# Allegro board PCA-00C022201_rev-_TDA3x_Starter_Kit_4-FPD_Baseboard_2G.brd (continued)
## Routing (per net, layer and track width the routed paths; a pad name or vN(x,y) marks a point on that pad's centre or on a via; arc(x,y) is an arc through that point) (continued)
VOUT1_D23: length 98.7
  TOP w0.127: v1(40.01,8.47) J14.25 ; U16.36 v1(99.75,59.18)
  INNER1 w0.127: v1(40.01,8.47) 40.01,10.87 40.26,11.11 40.26,13.98 48.07,21.79 v1(51.64,21.79) 51.64,22.15 51.05,22.73 51.05,31.5 55.37,35.81 59.94,35.81 86.49,62.36 97.79,62.36 99.75,60.4 v1(99.75,59.18)
  BOTTOM w0.127: J13.53 51.39,22.04 v1(51.64,21.79)
VOUT1_DE: length 93.2
  TOP w0.127: v1(92.84,42.86) 93.54,43.56 93.79,43.56 94.25,44.02 U16.2 ; v1(51.94,11.24) 51.94,12.51 51.31,13.14 46.8,13.14 45.01,11.36 J14.45
  INNER1 w0.127: v1(51.94,11.24) 51.94,10.44 51.82,10.31 51.69,10.31 51.56,10.19 51.56,9.93 51.69,9.81 51.82,9.81 51.94,9.68 51.94,9.53 52.7,8.76 52.96,8.76 53.09,8.89 53.09,9.27 53.21,9.4 53.47,9.4 53.59,9.27 53.59,8.89 53.72,8.76 53.98,8.76 54.1,8.89 54.1,9.27 54.23,9.4 54.48,9.4 54.61,9.27 54.61,8.89 54.74,8.76 54.99,8.76 55.12,8.89 55.12,9.27 55.24,9.4 55.5,9.4 55.63,9.27 55.63,8.89 55.75,8.76 56.01,8.76 62.48,15.24 66.67,15.24 74.42,22.99 74.42,23.62 75.06,24.26 75.06,30.48 75.18,30.61 75.69,30.61 75.82,30.73 75.82,30.99 75.69,31.11 75.18,31.11 75.06,31.24 75.06,31.5 86.42,42.86 87.57,42.86 87.7,42.99 87.7,44.07 87.83,44.2 88.08,44.2 88.21,44.07 88.21,42.99 88.34,42.86 88.59,42.86 88.72,42.99 88.72,44.32 88.84,44.45 89.1,44.45 89.23,44.32 89.23,42.99 89.35,42.86 89.61,42.86 89.73,42.99 89.73,44.32 89.86,44.45 90.11,44.45 90.24,44.32 90.24,42.99 90.37,42.86 90.62,42.86 90.75,42.99 90.75,44.32 90.88,44.45 91.13,44.45 91.26,44.32 91.26,42.99 91.38,42.86 91.64,42.86 91.77,42.99 91.77,43.69 91.89,43.81 92.15,43.81 92.27,43.69 92.27,42.99 92.4,42.86 v1(92.84,42.86)
VOUT1_FLD: length 45.5
  TOP w0.127: U48.19 80.04,20.61 79.82,20.83 R237.2 79.82,22.03 78.49,23.37 v1(75.06,23.37) ; J14.53 47.01,10.95 47.88,11.81 49.97,11.81 v1(50.55,11.24)
  INNER1 w0.127: v1(75.06,23.37) 75.06,22.99 66.87,14.8 62.67,14.8 56.13,8.26 52.58,8.26 50.55,10.29 v1(50.55,11.24)
VOUT1_HSYNC: length 92.5
  TOP w0.127: v1(94.74,43.56) 95.25,44.07 U16.4 ; v1(51.24,10.79) 51.24,11.3 50.29,12.26 47.18,12.26 46.01,11.09 J14.49
  INNER1 w0.127: v1(51.24,10.79) 51.24,11.3 51.75,11.81 52.32,11.81 52.58,11.56 52.58,10.13 52.43,9.98 52.43,9.8 52.61,9.62 52.79,9.62 53.08,9.91 53.08,11.56 53.2,11.68 53.46,11.68 53.58,11.56 53.58,10.03 53.71,9.91 53.96,9.91 54.09,10.03 54.09,11.56 54.22,11.68 54.47,11.68 54.6,11.56 54.6,10.03 54.73,9.91 54.98,9.91 55.11,10.03 55.11,11.56 55.23,11.68 55.49,11.68 55.62,11.56 55.62,10.03 55.74,9.91 56.52,9.91 56.72,10.11 56.72,10.29 56.14,10.87 56.14,11.05 56.32,11.23 56.5,11.23 56.93,10.79 57.4,10.79 62.29,15.68 66.48,15.68 73.91,23.11 73.91,23.75 74.61,24.45 74.61,31.69 86.3,43.37 87.95,45.02 94.61,45.02 94.81,45.21 94.81,46.41 94.93,46.54 95.19,46.54 95.31,46.41 95.31,44.13 v1(94.74,43.56)
VOUT1_VSYNC: length 93.7
  TOP w0.127: U16.5 v1(95.75,43.69) ; J14.47 45.51,11.22 46.99,12.7 50.55,12.7 v1(51.24,12)
  INNER1 w0.127: v1(95.75,43.69) 95.76,43.7 95.76,46.74 95.19,47.31 95.19,54.99 95.06,55.12 94.81,55.12 94.68,54.99 94.68,47.31 94.11,46.74 94.11,45.85 93.73,45.47 87.76,45.47 86.11,43.81 86.11,43.81 74.17,31.88 74.17,24.64 73.41,23.88 73.41,23.24 66.29,16.13 62.1,16.13 57.4,11.43 57.02,11.43 56.26,12.19 51.44,12.19 v1(51.24,12)
WARM_RESETN: length 1.6
  TOP w0.152: TP76.1 86.02,11.43 J14.169
XREF_CLK/TIMER3: length 43.4
  TOP w0.127: J14.124 v1(74.52,4.78) ; U9.44 91.56,28.18 91,27.62 90.3,27.62 TP14.1 89.28,27.43 R121.2
  BOTTOM w0.127: TP14.1 89.53,27.43 86.66,24.56 86.66,8.24 85.98,7.56 85.98,4.19 85.47,3.68 75.61,3.68 v1(74.52,4.78)
N16778655: length 1.3
  TOP w0.305: C1.1 110.93,15.37 110.79,15.51 U1.1
N16778658: length 7.3
  TOP w0.305: C1.2 v1(111.7,13.78)
  BOTTOM w0.305: v1(111.7,13.78) 107,13.78 v1(105.66,15.11)
N16779093: length 2.6
  TOP w0.305: R12.1 105.49,19.74 105.49,18.77 C6.1 105.59,18.67 106.11,18.67 106.39,18.39 U1.7
N16779143: length 1.2
  TOP w0.305: R13.1 U1.5
N16779358: length 1.3
  TOP w0.305: C5.1 111.5,18.39 U1.4
N16784059: length 3
  BOTTOM w0.381: U3.14 16.75,59.65 17.41,58.98 R28.1 R26.2
N16784098: length 1.6
  BOTTOM w0.254: U3.3 8.67,60.95 R24.2
N16784610: length 5.5
  BOTTOM w0.381: U3.13 17.24,60.3 17.78,59.75 R30.1
N16784791: length 11
  INNER2 w0.381: v2(14.22,58.42) 14.8,58.99 v1(23.18,58.99)
  BOTTOM w0.381: R30.2 R31.1 v1(23.18,58.99)
  vias: v1(12.06,63.5) v1(12.06,62.55) v1(12.06,61.59) v1(12.06,60.64) v1(12.06,59.69) v1(12.95,63.5) v1(12.95,62.55) v1(12.95,61.59) v1(12.95,60.64) v1(12.95,59.69) v1(13.84,63.5) v1(13.84,62.55) v1(13.84,61.59) v1(13.84,60.64) v1(13.84,59.69) v2(7.11,58.93) v2(7.56,68.33) v2(7.56,67.31) v2(7.56,66.29) v2(7.56,65.28) v2(8.57,68.33) v2(8.57,67.31) v2(8.57,66.29) v2(8.57,65.28) v2(8.64,58.93) v2(9.59,68.33) v2(9.59,67.31) v2(9.59,66.29) v2(9.59,65.28) v2(10.6,68.33) v2(10.6,67.31) v2(10.6,66.29) v2(10.6,65.28) v2(10.79,58.67) v2(11.62,68.33) v2(11.62,67.31) v2(11.62,66.29) v2(11.62,65.28) v2(11.94,58.67) v2(12.64,68.33) v2(12.64,67.31) v2(12.64,66.29) v2(12.64,65.28) v2(13.08,58.42) v2(13.08,57.15) v2(13.65,68.33) v2(13.65,67.31) v2(13.65,66.29) v2(13.65,65.28) v2(14.22,57.15) v2(14.67,68.33) v2(14.67,67.31) v2(14.67,66.29) v2(14.67,65.28) v2(15.37,57.15) v2(15.68,68.33) v2(15.68,67.31) v2(15.68,66.29) v2(15.68,65.28)
N16788418: length 1.8
  TOP w0.203: U5.9 98.4,4.09 98.99,3.49 C25.2
N16788506: length 1.3
  TOP w0.292: C22.2 97.15,3.18 U5.7
N16788509: length 1.6
  TOP w0.292: C22.1 98.32,2.9 97.65,3.49 U5.8
N16799359: length 1.1
  BOTTOM w0.127: R69.2 6.67,17.85 C77.1
N16799508: length 5.4
  BOTTOM w0.305: R63.2 7.82,13.46 7.82,9.25 L13.2
N16800770: length 1.1
  BOTTOM w0.127: C78.1 6.67,30.55 R70.2
N16800854: length 5.5
  BOTTOM w0.305: R65.2 7.82,26.16 7.82,21.93 L15.2
N16801557: length 1.1
  BOTTOM w0.127: R77.2 6.67,43.25 C91.1
N16801641: length 5.2
  BOTTOM w0.305: L23.2 7.82,34.63 7.82,38.84 R71.2
N16802378: length 1.1
  BOTTOM w0.127: R78.2 6.67,55.95 C92.1
N16802462: length 5.5
  BOTTOM w0.305: R73.2 7.82,51.51 7.82,47.3 L25.2
N16805253: length 1.3
  BOTTOM w0.152: R59.2 33.65,38.82 U7.1
N16808896: length 5.6
  BOTTOM w0.127: U6.5 31.9,29.8 31.9,30.99 30.82,32.07 R45.2
N16808937: length 4.8
  BOTTOM w0.152: R42.2 32.96,33.34 32.18,32.56 TP4.1 32.41,31.53 U6.6
N16828608: length 2.1
  TOP w0.152: U10.1 v1(98.3,67.5)
  BOTTOM w0.152: v1(98.3,67.5) 97.41,67.5 R90.2
N16828611: length 1.9
  TOP w0.152: U10.4 v1(98.3,63.69)
  BOTTOM w0.152: v1(98.3,63.69) 99.06,63.69 R91.2
N16829078: length 4.2
  TOP w0.381: R93.2 107.51,64.83 108.01,65.34 v1(108.01,65.6) 108.01,65.91 107.57,66.36 R92.2
  BOTTOM w0.381: C111.1 v1(108.01,65.6)
N16848362: length 2.4
  BOTTOM w0.152: J13.15 60.89,20.96 R112.2
N16871816: length 2.3
  TOP w0.254: U9.12 94.67,36.13 95.25,36.7 v1(95.25,37.01)
  BOTTOM w0.508: v1(95.25,37.01) R117.1
N16872796: length 2.6
  TOP w0.203: U13.8 v1(93.32,21.7)
  BOTTOM w0.254: R118.1 93.32,23.87 v1(93.32,21.7)
N16872856: length 4.7
  TOP w0.203: U13.5 93.46,19.82 94.44,18.85 95.15,18.85 95.63,18.36 R119.1 96.01,18.54 R120.2
N16877045: length 1.2
  TOP w0.127: U14.3 94.55,39.98 R233.1
N16921638: length 2.7
  BOTTOM w0.254: R25.2 17.97,60.64 17.67,60.95 U3.12
N16945191: length 1.5
  BOTTOM w0.305: C150.1 J24.12
N16950158: length 2.5
  BOTTOM w0.305: C151.1 J24.6
N16950163: length 2.5
  BOTTOM w0.305: J24.1 C152.1
N16950168: length 1.5
  BOTTOM w0.305: J24.7 C153.1
N16959967: length 3
  TOP w0.152: U16.3 v1(94.75,44.45)
  BOTTOM w0.152: v1(94.75,44.45) 95.5,44.45 95.89,44.83 R131.1
N16959972: length 3.4
  TOP w0.152: U16.10 v1(98.25,44.45)
  BOTTOM w0.152: R130.1 98.25,45.26 v1(98.25,44.45) 98.25,43.26 R134.1
N16959998: length 2
  TOP w0.127: U16.15 v1(100.75,44.58)
  BOTTOM w0.127: v1(100.75,44.58) 101.13,44.2 R132.2
N16960003: length 4
  TOP w0.127: U16.14 100.25,44.34 100.52,44.07 101.98,44.07 102.23,43.82 R133.2
N16960049: length 2.3
  TOP w0.152: R135.1 99.75,43.38 U16.13
N16962010: length 1.1
  TOP w0.279: 103.25,48.18 v1(104.39,48.18)
N16974466: length 2.1
  TOP w0.152: J21.9 87.3,56.83 v1(88.01,56.83)
  BOTTOM w0.152: v1(88.01,56.83) R151.1
N16989017: length 2.8
  TOP w0.152: U10.8 v1(101.35,67.5)
  BOTTOM w0.152: R166.1 100.52,67.5 v1(101.35,67.5) 102.17,67.5 R89.2
N17023402: length 8.5
  TOP w0.305: R10.2 R14.1 102.21,20.22 102.63,20.64 106.17,20.64 106.89,19.92 U1.6
N17041661: length 5.8
  TOP w0.152: R180.2 87.76,27.56 88.33,28.13 90.87,28.13 91.19,28.45 91.19,29.08 91.05,29.21 U9.43
N17043205: length 1.7
  TOP w0.305: D12.C v1(90.68,26.86)
  BOTTOM w0.305: v1(90.68,26.86) 90.68,26.16 R181.1
N17043208: length 1.5
  BOTTOM w0.305: J24.13 R182.1
N17043211: length 1.5
  BOTTOM w0.305: R183.1 J24.16
N17061008: length 2.4
  TOP w0.292: 34.98,14.1 34.98,14.1 U21.3
  TOP w0.381: TP44.1 34.98,13.54 R184.2
N17061570: length 1.2
  TOP w0.292: C179.1 39.39,14.1 U21.6
N17062531: length 2.7
  TOP w0.152: U22.2 v1(26.92,3.42)
  BOTTOM w0.152: R194.2 27.68,3.42 v1(26.92,3.42) 26.17,3.42 R193.1
N17062635: length 7.5
  TOP w0.152: U22.21 23.9,4.72 v1(26.16,6.99)
  BOTTOM w0.152: v1(26.16,6.99) R195.1 R196.2
N17083264: length 2
  TOP w0.152: R222.1 v1(42.99,42.55)
  BOTTOM w0.152: v1(42.99,42.55) 42.99,42.05 42.84,41.9 U28.4
N17084179: length 3.3
  TOP w0.152: J14.11 36.51,11.24 36.83,11.56 TP50.1
N17084298: length 1.8
  TOP w0.152: TP51.1 39.62,10.92 39.51,10.81 J14.23
N17084336: length 1.8
  TOP w0.152: J14.12 36.51,1.84 TP52.1
N17084566: length 2
  TOP w0.152: TP53.1 39.01,2.31 J14.22
N17086992: length 2.1
  TOP w0.152: J14.126 75.02,2.63 TP54.1
N17087001: length 1.8
  TOP w0.152: TP55.1 75.52,1.86 J14.128
N17088234: length 4.2
  BOTTOM w0.61: R223.1 123.19,3.81 MH1.1
N17088237: length 4.2
  BOTTOM w0.61: MH2.1 4.57,3.05 R224.1
N17088240: length 4.1
  TOP w0.61: R225.1 123.19,66.04 MH3.1
N17088243: length 4.3
  BOTTOM w0.61: MH4.1 3.81,64.14 R226.1
N17088661: length 4.1
  BOTTOM w0.61: R227.1 92.38,14.61 MH5.1
N17088663: length 4.1
  BOTTOM w0.61: R228.1 MH6.1
N17088675: length 4.6
  BOTTOM w0.61: MH7.1 92.38,63.62 R229.1
N17088677: length 4.1
  BOTTOM w0.61: MH8.1 R230.1
N17350751: length 13.7
  TOP w0.406: J23.7 19.74,65.73 J23.5
  BOTTOM w0.254: J23.9 19.42,68.4 ; J23.9 16.97,68.4 ; J23.9 18.19,67.27 ; J23.6 24.97,65.4 ; J23.6 23.57,65.4 ; J23.6 24.27,66.2 ; J23.8 26.72,68.4 ; J23.8 25.49,67.27 ; J23.8 24.27,68.4 ; 18.72,65.4 J23.7 ; J23.7 19.42,64.6 ; J23.7 19.42,66.2 ; J23.7 20.12,65.4
N17371221: length 2.3
  BOTTOM w0.152: U38.6 33.79,45.67 33.46,45.34 R102.1
N17371356: length 2.8
  BOTTOM w0.152: R105.1 35.75,45.28 35.5,45.53 35.12,45.53 34.79,45.85 U38.4
N17389734: length 2.2
  TOP w0.508: R249.2 26.34,61.54 R251.1 26.35,60.49 R247.1
N17389895: length 2.4
  TOP w0.508: R250.2 8.45,61.34 R248.1 R252.1
N17515572: length 1.9
  TOP w0.305: D18.C v1(101.41,2.03)
  BOTTOM w0.305: v1(101.41,2.03) 101.16,2.28 Q7.3
N17515594: length 1.8
  TOP w0.305: D18.A v1(103.53,2.92)
  BOTTOM w0.305: v1(103.53,2.92) 103.53,2.06 R259.2
N17515834: length 6.8
  TOP w0.305: D17.C v1(104.52,2.03)
  BOTTOM w0.305: v1(104.52,2.03) 104.52,2.86 101.16,6.22 Q8.3
N17515881: length 1.8
  TOP w0.305: D17.A v1(106.64,2.92)
  BOTTOM w0.305: v1(106.64,2.92) 106.64,2.06 R260.2
N17688900: length 1.7
  TOP w0.152: SW2.7 v1(9.65,3.17)
  BOTTOM w0.152: R204.2 v1(9.65,3.17)
N17688914: length 1.7
  TOP w0.152: 8.64,1.91 v1(9.65,1.91)
  BOTTOM w0.152: R203.1 v1(9.65,1.91)
N17750408: length 1.6
  BOTTOM w0.381: LR1.2 2.54,16.68 L17.1
N17835449: length 116
  TOP w0.381: J24.17 124.09,25.73 ; J24.17 124.09,23.68 ; J24.17 122.04,23.68 ; J24.17 122.04,25.73 ; 122.04,41.86 J24.18 ; J24.18 124.09,41.86 ; J24.18 124.09,39.81 ; J24.18 122.04,39.81
  GND1 w0.254: J24.18 124.09,39.81 ; J24.18 124.09,41.86 ; J24.18 122.04,41.86 ; J24.18 122.04,39.81 ; J24.17 124.09,23.68 ; J24.17 124.09,25.73 ; J24.17 122.04,23.68 ; J24.17 122.04,25.73
  INNER1 w0.381: 122.04,41.86 J24.18 ; J24.18 124.09,39.81 ; J24.18 124.09,41.86 ; J24.18 122.04,39.81 ; 122.04,25.73 J24.17 ; J24.17 124.09,23.68 ; J24.17 124.09,25.73 ; J24.17 122.04,23.68
  GND2 w0.254: J24.18 124.09,41.86 ; J24.18 124.09,39.81 ; J24.18 122.04,41.86 ; J24.18 122.04,39.81 ; J24.17 124.09,25.73 ; J24.17 122.04,23.68 ; J24.17 124.09,23.68 ; J24.17 122.04,25.73
  PWR1 w0.381: 122.04,23.68 J24.17 ; J24.17 124.09,25.73 ; J24.17 122.04,25.73 ; J24.17 124.09,23.68 ; 122.04,39.81 J24.18 ; J24.18 124.09,39.81 ; J24.18 122.04,41.86 ; J24.18 124.09,41.86
  PWR2 w0.381: 122.04,41.86 J24.18 ; J24.18 124.09,41.86 ; J24.18 122.04,39.81 ; J24.18 124.09,39.81 ; 122.04,23.68 J24.17 ; J24.17 122.04,25.73 ; J24.17 124.09,23.68 ; J24.17 124.09,25.73
  GND3 w0.254: 122.04,39.81 J24.18 ; J24.18 124.09,39.81 ; J24.18 124.09,41.86 ; J24.18 122.04,41.86 ; 122.04,25.73 J24.17 ; J24.17 124.09,25.73 ; J24.17 122.04,23.68 ; J24.17 124.09,23.68
  INNER2 w0.381: J24.18 124.09,41.86 ; J24.18 124.09,39.81 ; J24.18 122.04,39.81 ; J24.18 122.04,41.86 ; J24.17 124.09,23.68 ; J24.17 122.04,25.73 ; J24.17 122.04,23.68 ; J24.17 124.09,25.73
  GND4 w0.254: 122.04,25.73 J24.17 ; J24.17 124.09,25.73 ; J24.17 122.04,23.68 ; J24.17 124.09,23.68 ; J24.18 124.09,39.81 ; J24.18 122.04,39.81 ; J24.18 124.09,41.86 ; J24.18 122.04,41.86
  BOTTOM w0.381: 122.04,23.68 J24.17 ; J24.17 124.09,25.73 ; J24.17 122.04,25.73 ; J24.17 124.09,23.68 ; 122.04,41.86 J24.18 ; J24.18 124.09,39.81 ; J24.18 124.09,41.86 ; J24.18 122.04,39.81
  vias: v2(120.65,42.42) v2(122.17,42.93) v2(123.32,42.93) v2(124.46,42.93)
N17854884: length 3
  TOP w0.305: U20.2 108.9,58.16 v1(108.58,57.85) 107.89,57.85 R312.2
  BOTTOM w0.305: C177.1 v1(108.58,57.85)
N17856030: length 2
  TOP w0.305: v1(116.84,57.97) 116.65,58.16 U20.37
  BOTTOM w0.305: v1(116.84,57.97) 116.27,57.97 C176.1
N17857226: length 5.8
  TOP w0.127: J19.15 119.29,51.21 118.73,50.66 v1(117.09,50.66) U20.22
  BOTTOM w0.127: R313.2 v1(117.09,50.66)
N17857229: length 5.3
  TOP w0.127: J19.16 119.39,50.81 118.74,50.16 v1(118.24,50.16) U20.21
  BOTTOM w0.127: R314.2 v1(118.24,50.16)
N17857232: length 5.3
  TOP w0.127: J19.19 v1(119.13,49.61) 117.27,49.61 117.22,49.66 U20.20
  BOTTOM w0.127: v1(119.13,49.61) 119.38,49.36 R315.1
N17858343: length 9.4
  TOP w0.127: J26.14 58.55,61.91 59,61.46 U43.23 59,57.21 61.15,55.05 R278.1
N17858344: length 8.3
  TOP w0.127: J26.15 58.95,62.08 59.5,61.53 U43.22 59.5,57.47 60.71,56.26 R277.2
N17858345: length 7.2
  TOP w0.127: J26.16 59.35,62.25 60,61.6 U43.21 60,57.73 60.33,57.4 R276.2
N17858346: length 4.3
  TOP w0.127: J26.19 60.55,62.07 60.7,61.91 R275.2 R294.1 60.7,59.75 60.5,59.55 U43.20
N17880680: length 2.1
  TOP w0.279: U43.37 v1(52,59.82)
  BOTTOM w0.381: v1(52,59.82) 51.69,59.51 C221.1
N17880809: length 3.4
  TOP w0.279: U43.2 v1(52,51.69)
  BOTTOM w0.381: v1(52,51.69) 52.26,51.95 C223.1
  BOTTOM w0.508: C223.1 R280.2
N17882114: length 1.2
  TOP w0.305: v1(62.23,47.37) 61.79,46.93 U44.64
N17895085: length 7.5
  TOP w0.152: U44.58 63.58,43.93 63.82,43.69 R293.1 64.39,43.69 C252.1 66.17,43.69 67.71,42.15 Y2.1
N17895092: length 7.5
  TOP w0.152: U44.59 63.54,44.43 63.82,44.71 R293.2 64.39,44.7 C253.1 66.17,44.7 67.71,46.25 Y2.2
N17937761: length 1.2
  TOP w0.152: R238.1 78.37,17.54 U48.1
N17941586: length 11
  TOP w0.152: v1(119.44,64.33) 121.35,62.42 122.43,62.42 122.81,62.04 122.81,60.9 123.27,60.44 U41.1
  BOTTOM w0.152: v1(119.44,64.33) 119.44,65.09 118.24,66.29 R265.2 R296.1
N17941618: length 9.6
  TOP w0.152: U41.3 v1(124.78,61.74)
  BOTTOM w0.152: v1(124.78,61.74) 124.6,61.91 R295.1 120.84,61.91 118.75,64.01 118.75,64.52 118.24,65.02 R266.2
N17941727: length 3.6
  BOTTOM w0.152: R267.2 118.24,63.75 119.2,62.79 U42.6
N17941759: length 1.4
  BOTTOM w0.152: R268.2 117.73,61.97 117.9,61.8 U42.4
N17942689: length 2.9
  TOP w0.152: R299.2 v1(33.13,52.58)
  BOTTOM w0.152: v1(33.13,52.58) 33.13,51.28 33.29,51.12 U38.10
N17942746: length 2.9
  TOP w0.152: R300.2 34.29,53.26 v1(34.29,52.58)
  BOTTOM w0.152: U38.12 v1(34.29,52.58)
N17942762: length 2.3
  BOTTOM w0.152: R104.1 34.61,45.34 34.29,45.65 U38.5
N17942771: length 2.5
  BOTTOM w0.152: U38.7 33.29,46.31 32.32,45.34 R101.1
N17945605: length 2
  TOP w0.152: R301.2 29.09,57.4 29.59,56.9 U47.9
N17947242: length 1.6
  BOTTOM w0.381: L27.1 2.54,42.08 LR3.2
N17947474: length 1.6
  BOTTOM w0.381: LR4.2 2.54,54.78 L28.1
N17947670: length 1.6
  BOTTOM w0.381: LR2.2 2.54,29.38 L18.1
N17947891: length 1.6
  BOTTOM w0.381: LR5.2 2.54,15.07 LR1.1
N17947954: length 1.6
  BOTTOM w0.381: LR2.1 2.54,27.77 LR6.2
N17948346: length 1.6
  BOTTOM w0.381: LR4.1 2.54,53.17 LR8.2
N17948389: length 1.6
  BOTTOM w0.381: LR7.2 2.54,40.47 LR3.1
N17949147: length 2.2
  TOP w0.152: R304.1 69.94,66.78 U45.1
N17949152: length 2
  TOP w0.152: R303.1 69.29,67.25 U45.2
N17949167: length 2.2
  TOP w0.152: R302.1 68.64,66.79 U45.3
N17955828: length 2.6
  TOP w0.152: R306.2 v1(69.34,53.34)
  BOTTOM w0.152: U46.15 69.95,52.73 v1(69.34,53.34)
N17957422: length 1.7
  TOP w0.152: 8.64,4.45 v1(9.65,4.45)
  BOTTOM w0.152: R308.2 v1(9.65,4.45)
N18040269: length 1.1
  TOP w0.305: R325.1 103.38,19.81 R12.2
N18040280: length 1.1
  TOP w0.305: C7.1 104.41,18.74 R325.2
N18040766: length 2.8
  TOP w0.203: R326.2 95.45,2.46 R35.1
  TOP w0.292: U5.5 96.15,3.42 95.46,2.73 R35.1
N18041733: length 1.5
  TOP w0.203: R119.2 93.86,18.16 R327.1
N167880061: length 1.1
  TOP w0.203: R326.1 R33.2

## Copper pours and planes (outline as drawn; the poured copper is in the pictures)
DGND on TOP (solid shape): 113.51,46.63 115.32,46.63 116.23,45.72 117.35,45.72 117.35,43.94 117.09,43.69 113.54,43.69 113.54,45.21 112.55,46.2 112.55,49.02 113.51,49.02
DGND on TOP (solid shape): 37.69,15.75 37.69,13.74 38.73,13.74 38.73,13.27 40.07,13.27 40.07,12.12 40.02,12.03 39.91,12.03 39.55,12.11 39.22,11.94 38.64,11.94 38.23,12.12 37.82,11.94 36.83,11.94 36.83,15.75 36.96,15.88 37.57,15.88
DGND on TOP: 98.17,24 98.17,21.02 106.3,21.02 107.57,19.75 107.57,17.97 101.88,17.97 101.88,17.34 107.57,17.34 107.57,8 111.38,8 112.01,7.37 112.01,2.16 115.87,2.16 115.87,12.9 115.76,13.02 110.11,13.02 110.11,19.88 112.65,19.88 112.65,17.72 116.71,17.72 116.71,24
DGND on TOP: 43.99,31.24 40.56,31.24 40.56,28.07 42.09,28.07 42.09,25.27 43.99,25.27
DGND on TOP: 83.31,19.3 80.26,19.3 80.26,17.27 84.58,17.27 84.58,17.91 83.31,17.91
DGND on TOP: 88.07,22.23 88.07,24 89.85,25.78 92.14,25.78 92.14,22.07 92.7,21.51 92.7,18.35 90.87,18.35 90.87,19.96 91.73,19.96 91.83,20.07 91.83,21.08 91.73,21.18 90.87,21.18 90.87,21.78 90.42,22.23
DGND on TOP: 42.41,17.59 38.85,17.59 38.85,20.57 42.41,20.57
DGND on TOP: 30.21,34.73 28.31,34.73 28.31,36.39 30.21,36.39
DGND on TOP: 33.27,56.26 31.5,56.26 31.5,58.04 33.27,58.04
DGND on TOP: 60.07,47.75 50.93,47.75 50.93,38.61 60.07,38.61
DGND on TOP: 22.48,56.26 16.99,56.26 16.99,61.98 22.48,61.98
DGND on TOP: 96.14,1.78 96.14,2.79 96.47,3.12 96.47,4.32 96.01,4.32 96.01,6.1 96.52,6.1 96.52,11.56 100.2,11.56 101.22,10.54 101.22,7.11 98.55,7.11 98.3,7.37 97.47,7.37 97.28,7.18 97.28,6.1 97.79,6.1 97.79,4.32 96.82,4.32 96.82,1.98 96.96,1.84 98.93,1.84 99.12,2.03 99.12,2.79 100.14,2.79 100.14,1.84 99.69,1.4 96.52,1.4
DGND on TOP: 119.95,67.12 119.63,66.8 118.62,66.8 118.3,67.12 118.3,68.26 119.95,68.26
DGND on BOTTOM: 31.37,47.69 31.37,49.72 35.81,49.72 35.81,47.69
DGND on BOTTOM: 98.04,11.3 98.04,8.64 98.17,8.51 100.97,8.51 101.09,8.64 101.09,11.3 100.97,11.43 98.17,11.43
DGND on BOTTOM: 5.08,57.91 1.65,57.91 1.33,57.59 1.33,56.32 1.65,56.01 4.83,56.01 5.21,55.63 5.21,54.48 5.91,54.48 5.91,56.26 6.22,56.58 9.65,56.58 9.65,57.66 5.33,57.66
DGND on BOTTOM: 5.08,45.21 1.65,45.21 1.33,44.89 1.33,43.62 1.65,43.31 4.83,43.31 5.21,42.93 5.21,41.78 5.91,41.78 5.91,43.56 6.22,43.88 9.65,43.88 9.65,44.96 6.54,44.96 5.94,44.35
DGND on BOTTOM: 92.58,30.35 87.12,30.35 87.12,30.86 87.88,30.86 88.01,30.99 88.01,35.69 87.88,35.81 86.87,35.81 85.6,34.54 84.07,34.54 83.95,34.67 83.95,36.2 84.07,36.32 92.14,36.32 92.71,36.89 92.71,39.75 97.54,39.75 97.54,38.35 95.63,38.35 95.12,37.85 94.11,37.85 93.73,37.47 93.73,28.7 93.09,28.7 92.84,28.96 92.84,30.1
DGND on BOTTOM: 122.05,7.11 122.43,7.49 122.43,8.51 122.05,8.89 121.03,8.89 121.03,7.11
DGND on BOTTOM: 80.2,20.7 80.2,18.54 79.69,18.03 79.69,17.21 83.44,17.21 83.44,19.05 81.79,20.7
DGND on BOTTOM: 51.88,48.32 51.88,48.51 54.99,48.51 54.99,48.01 57.4,48.01 57.4,48.58 59.44,48.58 59.44,47.75 60.07,47.75 60.07,45.34 60.83,45.34 60.83,40.51 60.2,40.51 60.2,38.42 58.8,38.42 58.23,37.85 54.86,37.85 54.86,38.29 52.45,38.29 52.45,37.78 51.18,37.78 50.16,38.8 50.16,48.32
DGND on BOTTOM: 25.91,56.77 25.91,59.56 26.04,59.69 27.05,59.69 27.18,59.56 27.18,56.77 27.05,56.64 26.04,56.64
DGND on BOTTOM: 87.44,15.75 87.82,15.37 88.84,15.37 89.22,15.75 89.22,16.76 87.44,16.76
DGND on BOTTOM: 107.95,12.45 107.95,8.26 108.2,8 111.38,8 112.01,7.37 112.01,2.16 115.63,2.16 115.63,12.76 115.44,12.95 108.46,12.95
DGND on BOTTOM: 35.43,66.93 35.05,66.55 35.05,65.53 35.43,65.15 36.58,65.15 36.58,66.93
DGND on BOTTOM: 30.54,56.32 30.54,57.47 31.62,57.47 31.62,57.91 33.02,57.91 33.53,57.4 35.05,57.4 35.18,57.28 35.18,56.13 35.05,56.01 30.86,56.01
DGND on BOTTOM: 5.08,19.81 1.65,19.81 1.33,19.49 1.33,18.22 1.65,17.91 4.83,17.91 5.21,17.53 5.21,16.38 5.91,16.38 5.91,18.16 6.22,18.48 9.65,18.48 9.65,19.56 6.54,19.56 5.94,18.95
DGND on BOTTOM: 119.25,46.29 124.84,46.29 124.84,44.58 119.25,44.58
DGND on BOTTOM: 5.08,32.51 1.65,32.51 1.33,32.19 1.33,30.92 1.65,30.61 4.83,30.61 5.21,30.23 5.21,29.08 5.91,29.08 5.91,30.86 6.22,31.18 9.65,31.18 9.65,32.26 6.54,32.26 5.94,31.65
DGND on BOTTOM: 102.11,56.77 102.87,56.01 102.87,46.04 97.85,46.04 97.85,46.86 97.41,47.31 94.68,47.31 94.04,46.67 94.04,46.1 93.34,46.1 93.34,46.61 91.38,46.61 91.38,55.18 92.96,56.77
DGND on BOTTOM: 8.57,1.91 8.19,2.29 7.18,2.29 6.79,1.91 6.79,0.57 8.57,0.57
DGND on BOTTOM: 5.97,61.79 4.38,61.79 4.38,60.01 5.08,60.01 5.97,60.9
DGND on BOTTOM: 26.99,13.46 26.61,13.84 25.59,13.84 25.21,13.46 25.21,12.45 26.99,12.45
DGND on BOTTOM: 75.56,66.42 75.56,68.58 78.11,68.58 78.11,66.42
DGND on BOTTOM: 90.11,61.59 90.11,63.37 88.46,63.37 88.46,62.36 89.22,61.59
DGND on GND1: 0.51,0.51 0.51,69.34 126.49,69.34 126.49,0.51
DGND on GND2: 0.51,69.34 126.49,69.34 126.49,0.51 0.51,0.51 0.51,14.88 3.45,14.88 3.45,16.87 0.51,16.87 0.51,27.58 3.45,27.58 3.45,29.57 0.51,29.57 0.51,40.28 3.45,40.28 3.45,42.27 0.51,42.27 0.51,52.98 3.45,52.98 3.45,54.97 0.51,54.97
DGND on GND3, GND4: 0.51,69.34 126.49,69.34 126.49,0.51 0.51,0.51
DGND on INNER2: 126.49,69.34 126.49,0.51 89.03,0.51 89.03,3.56 67.56,25.02 67.56,34.92 77.22,44.58 77.22,54.99 77.72,55.5 106.24,55.5 106.24,69.34 ; 1 cut-out
DGND on INNER2: 27.43,69.34 27.43,0.51 0.51,0.51 0.51,69.34
DVDD_HDMI_IN on BOTTOM: 63.44,36.39 61.98,36.39 61.98,38.42 60.71,38.42 60.71,40.13 61.34,40.13 61.34,41.34 62.61,41.34 62.61,39.37 63.44,38.54
DVDD_HDMI_IN on PWR1: 48.13,42.93 48.51,42.55 49.53,42.55 54.61,37.47 54.61,36.2 54.86,35.94 55.63,35.94 57.53,37.85 61.98,37.85 62.56,38.43 62.56,39.09 62.05,39.6 62.05,40.26 62.66,40.87 62.66,45.03 62.36,45.34 50.67,45.34 48.9,43.56 48.39,43.56 48.13,43.31
PVDD_HDMI_IN on BOTTOM: 64.26,42.99 63.69,42.99 62.67,41.97 61.34,41.97 61.34,43.94 61.53,44.13 64.26,44.13
VDD1P1 on BOTTOM: 94.23,34.01 95.28,34.01 95.57,33.72 95.57,32.45 95.3,32.18 94.23,32.18
VDD1P1 on BOTTOM: 87.5,33.15 86.23,33.15 86.11,33.02 86.11,31.37 86.23,31.24 87.5,31.24
VDD1P1 on BOTTOM: 89.66,38.61 89.66,36.83 84.65,36.83 84.65,38.48 85.15,38.99 89.28,38.99
VDD1P1 on BOTTOM: 90.42,28.7 90.42,29.84 92.33,29.84 92.33,28.7 92.2,28.57 90.55,28.57
VDD1P1 on PWR1: 88.01,35.43 88.01,33.66 87.5,33.15 86.23,33.15 86.11,33.02 86.11,32.13 87.88,30.35 89.53,30.35 90.42,29.46 90.42,28.7 90.55,28.57 92.2,28.57 95.5,31.88 95.5,33.66 92.84,36.32 90.42,36.32 89.66,37.08 89.66,37.85 89.53,37.97 86.87,37.97 86.61,37.72 86.61,36.83
VDD_1V1 on TOP: 26.72,18.41 24.43,18.41 24.43,20.32 25.32,21.21 26.47,21.21 26.47,20 26.72,19.75
VDD_1V1 on TOP: 36.69,18.8 35.93,18.03 33.9,18.03 33.9,21.15 35.23,21.15 36.69,19.68
VDD_1V1 on TOP: 41.58,27.56 41.58,25.27 38.98,25.27 38.98,26.73 39.8,27.56
VDD_1V1 on TOP: 95.44,7.05 92.46,7.05 92.46,10.41 93.09,11.05 94.11,11.05 94.61,11.56 96.14,11.56 96.14,7.75
VDD_1V1 on BOTTOM: 88.52,39.88 88.39,39.75 86.36,39.75 86.23,39.88 86.23,41.02 88.52,41.02
VDD_1V1 on PWR2: 91.31,8 90.68,8.64 88.01,8.64 79.76,16.89 41.66,16.89 41.66,17.27 40.13,18.8 35.31,18.8 33.91,20.19 28.57,20.19 26.8,18.41 26.16,18.41 25.78,18.8 25.78,25.78 28.07,28.07 66.29,28.07 79.57,41.34 88.77,41.34 88.77,23.62 87.12,21.97 87.12,16.26 89.66,13.72 95.12,13.72 95.12,8.38 94.74,8
VDD_1V8 on TOP (solid shape): 36.56,14.48 35.61,14.48 35.61,14.86 35.23,15.24 34.34,15.24 34.34,15.88 34.49,15.88 34.5,15.81 34.51,15.75 34.53,15.69 34.56,15.64 34.59,15.59 34.63,15.54 34.67,15.5 34.73,15.46 34.78,15.43 34.84,15.41 34.9,15.4 34.96,15.39 35.02,15.39 35.08,15.4 35.14,15.42 35.2,15.45 35.25,15.48 35.3,15.52 35.34,15.56 35.38,15.61 35.41,15.67 35.43,15.72 35.45,15.78 35.46,15.84 35.46,15.91 35.45,15.97 35.43,16.03 35.41,16.08 35.38,16.14 35.34,16.19 35.3,16.23 35.25,16.27 35.2,16.3 35.14,16.33 35.08,16.35 35.02,16.36 34.96,16.36 34.9,16.35 34.84,16.34 34.78,16.32 34.73,16.29 34.67,16.25 34.63,16.21 34.59,16.16 34.56,16.11 34.53,16.06 34.51,16 34.5,15.94 34.49,15.88 34.34,15.88 34.34,16.64 36.56,16.64
VDD_1V8 on TOP: 36.14,2.92 35.38,2.92 35.38,4.39 34.66,4.39 34.66,5.27 36.14,5.27
VDD_1V8 on BOTTOM: 36.12,4.51 34.23,4.51 31.95,6.78 31.95,10.67 33.78,12.5 33.78,16 34.04,16.26 35.74,16.26 35.74,17.32 37.57,17.32 37.57,16.54 37.97,16.13 39.24,16.13 39.24,9.78 35.36,9.78 35.04,9.46 35.04,6.41 35.36,6.1 36.12,6.1
VDD_2V5 on TOP: 92.52,22.23 93.98,22.23 94.36,21.84 97.16,21.84 97.16,26.86 94.23,26.86 94.23,25.78 92.52,25.78
VDD_2V5 on BOTTOM: 96.77,27.94 94.74,27.94 94.42,27.62 94.42,26.42 94.68,26.16 96.84,26.16 97.09,26.42 97.09,27.62
VDD_3V3 on TOP: 36.14,7.3 35.38,7.3 35.38,10.54 36.14,10.54
VDD_3V3 on TOP: 44.69,31.62 41.07,31.62 41.07,32.89 44.69,32.89
VDD_3V3 on BOTTOM: 51.18,50.42 51.18,51.5 51.88,51.5 52.32,51.94 53.98,51.94 53.98,50.8 53.85,50.67 53.53,50.67 53.28,50.42
VDD_3V3 on BOTTOM: 104.27,45.09 104.27,43.94 107.06,43.94 107.06,45.09 106.81,45.34 104.52,45.34
VDD_3V3 on BOTTOM: 100.77,57.28 100.77,58.42 101.09,58.74 103.82,58.74 104.58,57.98 104.58,56.52 103.06,56.52 102.3,57.28
VDD_3V3 on BOTTOM: 49.4,35.56 48.01,35.56 47.62,35.94 47.62,37.66 49.4,37.66
VDD_3V3 on BOTTOM: 91.12,46.1 91.12,44.45 91.38,44.2 94.23,44.2 95.19,45.15 95.19,45.78 95.44,46.04 97.35,46.04 97.35,46.8 97.22,46.93 94.93,46.93 94.36,46.35 94.36,45.85 94.17,45.66 92.77,45.66 92.77,46.1
VDD_3V3 on BOTTOM: 78.61,66.42 78.61,68.83 79.63,68.83 80.14,69.34 81.28,69.34 81.79,68.83 82.17,68.83 82.17,67.31 81.28,66.42
VDD_3V3 on BOTTOM: 84.39,29.15 85.92,29.15 86.11,28.96 86.11,27.69 85.92,27.5 84.39,27.5
VDD_3V3 on PWR1: 26.42,11.56 26.42,63.25 31.62,68.45 78.74,68.45 79.63,69.34 81.66,69.34 83.19,67.82 121.92,67.82 121.92,44.7 118.62,44.7 118.62,43.05 106.81,43.05 106.81,1.4 9.65,1.4 9.65,8.64 23.5,8.64
VDD_5V0 on TOP (solid shape): 118.57,48.31 118.57,47.14 118.39,46.96 113.77,46.96 113.77,49.09 117.79,49.09
VDD_5V0 on INNER1: 113.28,48.64 100.46,48.64 100.46,60.58 97.54,63.5 97.54,65.66 103.25,65.66 119.13,49.78 119.13,46.61 113.28,46.61
VDD_5V0 on INNER2: 105.54,63.37 105.54,56.01 80.39,56.01 76.33,60.07 73.41,60.07 64.39,51.05 50.93,51.05 50.55,51.44 50.55,56.64 51.31,57.4 61.98,57.4 68.96,64.39 84.2,64.39 87.76,60.83 94.74,60.83 97.66,63.75 97.66,65.02 98.04,65.41 103.5,65.41
VDD_BB_1V8 on TOP (solid shape): 42.21,15.62 41.14,14.54 38.85,14.54 38.79,14.48 38,14.48 38,15.18 39.7,15.18 39.7,15.11 39.72,15.05 39.74,15 39.76,14.94 39.8,14.89 39.84,14.84 39.88,14.8 39.93,14.76 39.99,14.73 40.05,14.71 40.11,14.7 40.17,14.69 40.23,14.7 40.29,14.71 40.35,14.72 40.41,14.75 40.46,14.78 40.51,14.82 40.55,14.86 40.59,14.91 40.62,14.97 40.64,15.02 40.66,15.08 40.66,15.15 40.66,15.21 40.66,15.27 40.64,15.33 40.62,15.39 40.59,15.44 40.55,15.49 40.51,15.53 40.46,15.57 40.41,15.6 40.35,15.63 40.29,15.65 40.23,15.66 40.17,15.66 40.11,15.65 40.05,15.64 39.99,15.62 39.93,15.59 39.88,15.55 39.84,15.51 39.8,15.47 39.76,15.41 39.74,15.36 39.72,15.3 39.7,15.24 39.7,15.18 38,15.18 38,15.75 38.99,15.75 39.29,16.05 39.29,17.14 42.21,17.14
VDD_BB_1V8 on TOP: 25.15,33.78 26.8,33.78 26.8,29.97 26.67,29.84 25.53,29.84 24.82,30.56 24.82,33.45
VDD_BB_1V8 on TOP: 32.26,33.21 30.66,33.21 30.66,36.39 32.26,36.39
VDD_BB_1V8 on BOTTOM: 62.8,49.91 62.8,48.13 61.28,48.13 61.28,50.16 62.55,50.16
VDD_BB_1V8 on BOTTOM: 66.23,44.64 63.18,44.64 63.18,45.66 63.37,45.85 64.71,45.85 64.71,47.94 66.23,47.94
VDD_BB_1V8 on BOTTOM: 61.47,36.39 59.5,36.39 59.5,38.04 61.47,38.04
VDD_BB_1V8 on PWR1: 86.49,40.13 94.36,40.13 94.61,39.88 96.77,39.88 96.77,42.67 96.39,43.05 87,43.05 86.49,42.55
VDD_BB_1V8 on PWR2: 88.77,43.94 86.11,46.61 69.85,46.61 66.8,49.66 61.09,49.66 55.5,44.07 10.41,44.07 10.41,8.38 30.99,8.38 34.73,12.13 40.45,12.13 41.27,12.95 41.27,17.14 40.01,18.41 35.18,18.41 33.78,19.81 28.7,19.81 26.92,18.03 26.04,18.03 25.4,18.67 25.4,25.91 27.94,28.45 66.17,28.45 79.44,41.72 88.77,41.72
VDD_BB_3V3 on TOP (solid shape): 112.27,44.07 112.01,43.81 108.9,43.81 108.46,44.26 108.46,46.51 111.38,46.51 111.51,46.63 112.27,46.63
VDD_BB_3V3 on TOP: 111.51,7.11 111.12,7.49 101.73,7.49 101.73,3.43 107.82,3.43 107.82,2.16 111.51,2.16
VDD_BB_3V3 on TOP: 98.17,4.83 100.2,4.83 101.6,3.43 101.73,3.43 101.73,6.6 98.55,6.6 98.04,6.1 98.04,4.95
VDD_BB_3V3 on TOP: 35.13,7.3 33.77,7.3 33.77,11.29 34.23,11.75 35.42,11.75 35.81,12.14 35.81,13.74 36.42,13.74 36.42,11.79 36.07,11.43 36.07,10.79 35.13,10.79
VDD_BB_3V3 on TOP: 90.49,21.59 90.36,21.72 88.07,21.72 88.07,19.68 89.92,19.68 90.17,19.94 90.17,20.19 90.6,20.62 91.55,20.62 91.55,20.88 91.5,20.93 90.49,20.93
VDD_BB_3V3 on INNER1: 106.81,43.05 106.81,22.48 111.51,22.48 111.51,2.16 103.5,2.16 95.38,10.29 95.38,41.4 97.03,43.05 97.03,45.34 99.82,48.13 112.78,48.13 112.78,43.05 ; 1 cut-out
VDD_BB_3V3 on PWR2: 112.01,1.78 112.01,4.57 109.47,7.11 106.3,7.11 100.46,12.95 100.46,16 93.6,22.86 88.52,22.86 82.17,16.51 41.66,16.51 41.66,12.7 40.64,11.68 34.8,11.68 32.51,9.4 32.51,1.78
VDD_SW_FPD on BOTTOM: 20.19,38.76 21.69,38.76 22.1,38.35 22.1,37.34 21.72,36.96 20.93,36.96 20.93,35.56 23.18,35.56 23.62,36 23.62,38.48 22.3,39.8 20.19,39.8
VDD_SW_FPD on BOTTOM: 20.19,26.06 21.69,26.06 22.1,25.65 22.1,24.64 21.72,24.26 20.93,24.26 20.93,22.86 23.62,22.86 23.62,25.65 22.17,27.1 20.19,27.1
VDD_SW_FPD on BOTTOM: 20.19,51.46 21.69,51.46 22.1,51.05 22.1,50.04 21.72,49.66 20.93,49.66 20.93,48.26 23.62,48.26 23.62,51.18 22.3,52.5 20.19,52.5
VDD_SW_FPD on BOTTOM: 20.19,13.36 21.69,13.36 22.1,12.95 22.1,11.94 21.72,11.56 20.93,11.56 20.93,10.16 23.62,10.16 23.62,13.08 22.3,14.4 20.19,14.4
VDD_SW_FPD on BOTTOM: 10.54,64.39 6.99,64.39 6.86,64.26 6.86,62.23 7.05,62.04 10.79,62.04 10.79,64.14
VDD_SW_FPD on PWR1: 3.81,9.14 3.81,56.39 2.54,56.39 2.54,61.59 3.81,62.87 5.08,62.87 7.11,64.9 14.99,64.9 18.54,61.34 23.5,61.34 25.91,58.93 25.91,11.81 23.24,9.14
VDD_USB_3V3 on BOTTOM: 31.62,58.29 31.62,58.67 31.24,59.05 30.61,59.05 30.23,59.44 29.65,59.44 29.65,60.33 31.11,60.33 31.37,60.07 32.38,60.07 32.64,60.33 35.69,60.33 37.59,58.42 37.59,49.02 36.2,49.02 36.2,57.15 35.05,58.29
VDD_USB_5V0 on BOTTOM: 28.26,58.99 30.04,58.99 30.35,58.67 31.18,58.67 31.31,58.55 31.31,57.85 30.48,57.85 30.23,57.59 30.23,56.2 28.26,56.2
VDD_USB_5V0 on PWR1: 30.61,62.99 30.61,55.88 26.42,55.88 26.42,59.18 23.75,61.85 18.92,61.85 18.92,66.17 27.43,66.17
VDD_VIN on TOP: 116.71,17.34 111.51,17.34 111.32,17.14 110.49,17.14 110.36,17.02 110.36,16.57 110.49,16.45 111.32,16.45 111.76,16 111.76,14.54 112.78,13.53 116.04,13.53 116.46,13.11 116.46,2.16 119.13,2.16 119.13,14.92
VDD_VIN on BOTTOM: 111.51,14.86 111.51,16.38 112.14,17.02 117.09,17.02 119.25,14.86 119.25,2.16 116.27,2.16 116.27,13.27 115.7,13.84 114.17,13.84 113.41,14.61 111.76,14.61
VDD_VIN on BOTTOM: 15.11,62.04 15.11,64.14 15.37,64.39 18.92,64.39 19.05,64.26 19.05,62.23 18.86,62.04
VDD_VIN on PWR2: 120.78,1.78 112.39,1.78 112.39,4.7 109.6,7.49 106.43,7.49 100.84,13.08 100.84,16.26 93.85,23.24 89.15,23.24 89.15,44.07 86.23,46.99 69.98,46.99 66.93,50.04 60.96,50.04 55.37,44.45 10.41,44.45 10.41,66.42 106.81,66.42 106.81,22.48 116.97,22.48 120.78,18.67
VDDA1P8 on INNER2: 95.25,37.85 95.25,29.21 93.85,27.81 93.22,27.81 92.84,28.19 92.84,37.47 93.47,38.1 95,38.1
VDDA2P5 on BOTTOM: 94.23,36.2 94.23,34.42 95.44,34.42 95.95,33.91 95.95,32.32 95.48,31.85 95.1,31.85 95.02,31.78 94.23,31.78 94.23,28.7 96.27,28.7 96.27,30.23 97.03,30.99 97.03,37.85 95.89,37.85 95.89,36.83 95.25,36.2
VDDIO_960 on TOP: 35.94,35.94 34.48,35.94 34.16,35.62 32.83,35.62 32.7,35.75 32.7,38.23 33.02,38.54 33.97,38.54 33.97,37.47 34.54,36.89 35.94,36.89
VDDIO_960 on INNER2: 38.86,28.32 38.86,29.84 38.1,30.61 36.7,30.61 34.67,32.64 34.67,38.35 32.89,40.13 30.35,40.13 29.72,39.5 29.72,30.48 31.88,28.32
VDDIO_HDMI_IN on BOTTOM: 54.42,36.13 53.85,35.56 49.91,35.56 49.91,37.66 50.67,37.66 50.93,37.4 52.83,37.4 52.83,37.91 54.42,37.91
VDDIO_HDMI_IN on PWR1: 45.97,41.27 49.59,37.66 49.59,36.39 51.82,34.16 62.61,34.16 71.37,42.93 71.37,60.26 70.29,61.34 67.56,61.34 61.34,55.12 61.34,49.91 50.61,49.91 50.04,50.48 50.04,53.34 49.66,53.72 48.39,53.72 45.97,51.31
VDDIO_PHY on BOTTOM: 90.04,29.84 90.04,28.7 89.15,27.81 86.87,27.81 86.87,29.84
VDDIO_PHY on BOTTOM: 87.5,33.53 86.23,33.53 86.11,33.66 86.11,34.04 86.87,34.8 86.87,35.18 87,35.31 87.5,35.31
VDDIO_PHY on BOTTOM: 90.04,36.83 90.04,39.12 90.3,39.37 92.2,39.37 92.2,38.1 91.95,37.85 91.95,36.83
VDDIO_PHY on PWR1: 97.03,39.24 97.03,26.42 95,24.38 88.27,24.38 85.6,27.05 85.6,29.08 84.2,30.48 84.2,38.23 85.72,39.75 94.23,39.75 94.49,39.5 96.77,39.5
(no net) on TOP: 36.83,15.75 36.96,15.88 37.57,15.88 37.69,15.75 37.69,13.74 38.73,13.74 38.73,13.27 40.07,13.27 40.07,11.94 36.83,11.94
(no net) on TOP: 108.46,48.26 110.55,48.26 111.53,47.28 112.29,47.28 112.29,46.95 108.46,46.95
(no net) on TOP: 34.34,15.24 34.34,16.64 36.56,16.64 36.56,14.48 35.61,14.48 35.61,14.86 35.23,15.24
(no net) on TOP: 113.77,49.09 117.79,49.09 118.57,48.31 118.57,47.14 118.39,46.96 113.77,46.96
(no net) on TOP: 108.46,46.51 111.38,46.51 111.51,46.63 112.27,46.63 112.27,44.07 112.01,43.81 108.9,43.81 108.46,44.26
(no net) on TOP: 112.55,49.02 113.51,49.02 113.51,46.63 115.32,46.63 116.23,45.72 117.35,45.72 117.35,43.94 117.09,43.69 113.54,43.69 113.54,45.21 112.55,46.2
(no net) on TOP: 38,14.48 38,15.75 38.99,15.75 39.29,16.05 39.29,17.14 42.21,17.14 42.21,15.62 41.14,14.54 38.85,14.54 38.79,14.48
CVDD_HDMI_IN on BOTTOM: 51.44,48.77 49.15,48.77 49.15,50.04 52.26,50.04 52.51,50.29 52.64,50.29 52.7,50.23 52.7,48.96 51.44,48.96
CVDD_HDMI_IN on BOTTOM: 58.48,50.48 60.77,50.48 60.77,48.13 59.82,48.13 59.82,48.96 58.48,48.96
CVDD_HDMI_IN on PWR1: 49.02,48.77 49.28,48.51 59.44,48.51 59.94,48.01 60.71,48.01 60.96,48.26 60.96,50.29 49.28,50.29 49.02,50.04
HDMI_IN_5V0 on INNER1: 65.41,64.39 65.41,46.61 64.64,45.85 61.09,45.85 59.56,47.37 59.56,64.39
TVDD on BOTTOM: 105.14,55.77 105.47,55.44 105.47,50.36 103.31,50.36 103.31,55.77
TVDD_HDMI_IN on BOTTOM: 53.09,48.96 53.09,49.66 53.72,50.29 54.04,50.29 54.36,50.61 54.36,51.94 56.2,51.94 58.1,50.04 58.1,48.96
N16778658 on TOP: 106.93,14.67 105.98,14.67 105.98,16.13 106.36,16.51 107.19,16.51 107.31,16.64 107.31,16.89 107.19,17.02 105.41,17.02 104.27,15.88 104.27,14.67 102.36,14.67 102.36,8.95 106.93,8.95
N16782242 on TOP (solid shape): 111.53,47.28 112.29,47.28 112.29,46.95 108.46,46.95 108.46,48.26 110.55,48.26
N16784791 on TOP: 12.7,56.26 12.7,58.36 6.48,58.36 6.48,59.56 9.4,59.56 10.54,60.71 10.54,64.26 10.03,64.77 7.24,64.77 7.24,68.96 16,68.96 16,64.01 16.26,64.01 16.26,56.26
N16784791 on BOTTOM: 11.43,60.52 9.33,60.52 9.33,60.07 11.11,60.07 11.11,59.31 10.92,59.12 9.08,59.12 8.64,59.56 6.48,59.56 6.48,58.04 10.03,58.04 10.03,56.77 16.51,56.77 16.51,58.17 15.88,58.8 14.86,58.8 14.48,59.18 14.48,64.26 15.11,64.9 16,64.9 16,68.96 7.24,68.96 7.24,64.9 10.79,64.9 11.43,64.26
N16787891 on TOP: 95.63,5.33 94.68,5.33 94.6,5.26 92.65,5.26 92.65,6.4 94.46,6.4 94.77,6.1 95.63,6.1 95.76,5.97 95.76,5.46
N16799482 on BOTTOM: 3.94,15.3 3.94,12.52 2.01,10.59 3.45,9.14 7.24,12.93 6.68,13.49 6.68,14.22 7.15,14.69 6.54,15.3
N16799508 on BOTTOM: 4.48,8.12 5.94,6.65 6.55,7.26 13.51,7.26 13.51,13.94 14.38,14.81 14.38,15.57 11.94,15.57
N16799567 on BOTTOM: 14.73,15.57 18.69,15.57 19.53,14.73 19.53,13.36 19.2,13.03 19.2,12.17 19.63,11.73 20.4,11.73 20.4,10.16 18.67,10.16 18.14,9.63 18.14,7.26 15.57,7.26 15.57,13.97 14.73,14.81
N16800832 on BOTTOM: 3.94,28 3.94,25.2 2.01,23.27 3.45,21.82 7.24,25.6 6.6,26.24 6.6,26.95 7.1,27.44 6.54,28
N16800854 on BOTTOM: 4.48,20.79 5.94,19.33 6.58,19.96 13.51,19.96 13.51,26.64 14.38,27.51 14.38,28.27 11.96,28.27
N16800876 on BOTTOM: 14.73,28.27 18.59,28.27 19.53,27.33 19.53,26.01 19.2,25.68 19.2,24.87 19.63,24.43 20.4,24.43 20.4,22.86 18.67,22.86 18.14,22.33 18.14,19.96 15.57,19.96 15.57,26.67 14.73,27.51
N16801619 on BOTTOM: 3.94,40.7 3.94,37.9 2.01,35.97 3.45,34.52 7.24,38.3 6.65,38.89 6.65,39.4 7.23,39.97 6.49,40.7
N16801641 on BOTTOM: 4.48,33.49 5.94,32.03 6.58,32.66 13.51,32.66 13.51,39.29 14.38,40.16 14.38,40.97 11.96,40.97
N16801663 on BOTTOM: 14.73,40.97 18.59,40.97 19.53,40.03 19.53,38.71 19.2,38.38 19.2,37.57 19.81,36.96 20.4,36.96 20.4,35.56 18.67,35.56 18.14,35.03 18.14,32.66 15.57,32.66 15.57,39.29 14.73,40.13
N16802440 on BOTTOM: 3.94,53.4 3.94,50.57 2.01,48.64 3.45,47.19 7.24,50.98 6.53,51.69 6.53,52.27 7.04,52.78 6.41,53.4
N16802462 on BOTTOM: 4.48,46.16 5.94,44.7 6.6,45.36 13.51,45.36 13.51,51.99 14.38,52.86 14.38,53.67 11.99,53.67
N16802472 on BOTTOM: 14.73,53.67 18.59,53.67 19.53,52.73 19.53,51.41 19.2,51.08 19.2,50.27 19.81,49.66 20.4,49.66 20.4,48.26 18.67,48.26 18.14,47.73 18.14,45.36 15.57,45.36 15.57,51.99 14.73,52.83
N16872761 on TOP: 93.88,20.68 94.41,20.42 96.96,20.42 96.96,21.44 94.37,21.44 93.89,20.95 92.98,20.95 92.98,20.68
N16962010 on BOTTOM: 103.38,48.64 103.38,46.1 106.05,46.1 106.05,47.12 104.52,48.64
N17350751 on BOTTOM: 18.52,64.49 16.51,66.5 16.51,69.34 27.89,69.34 27.89,65.96 26.42,64.49
N17835449 on TOP, BOTTOM, INNER1, PWR1, PWR2, INNER2: 126.49,44.07 126.49,22.86 119.25,22.86 119.25,44.07
N17835449 on GND1, GND2, GND3, GND4: 119.25,22.86 119.25,44.07 126.49,44.07 126.49,22.86
N17882114 on BOTTOM: 63.12,46.23 62.74,45.85 60.58,45.85 60.58,47.75 62.8,47.75 63.12,47.43

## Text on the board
BOTTOM: PN:PCB-00C022201 | REV -
User.Comments: CR_3V3_1 | CR_5V0_1 | CR_2V5_1 | CR_1V1_1
Ref Des/Assembly Top: DesignCore | TM | REV | 4-FPD BASEBOARD 2G | ASSY:PCA-00C022201 | SN | TDA3x STARTER KIT | VIN1 | VIN2 | VIN3 | VIN4 | HDMI | IN | OUT
Ref Des/Silkscreen Top: DesignCore | TM | REV | 4-FPD BASEBOARD 2G | ASSY:PCA-00C022201 | SN | TDA3x STARTER KIT | VIN1 | VIN2 | VIN3 | VIN4 | HDMI | IN | OUT | 12V | 3A | MIN
PAGE_OUTLINE: SOLDERPASTE TOP
DISPLAY_TOP: SOLDERMASK TOP
DISPLAY_BOTTOM: SOLDERMASK BOTTOM (VIEWED FROM BOTTOM SIDE)
DIMENSION: SOLDERPASTE BOTTOM (VIEWED FROM BOTTOM SIDE)
User.6: ASSEMBLY TOP
User.7: ASSEMBLY BOTTOM (VIEWED FROM BOTTOM SIDE)
User.8: POWER 1
User.9: TOP COPPER
User.10: GROUND 1
User.11: SILKSCREEN BOTTOM (VIEWED FROM BOTTOM SIDE)
User.12: SILKSCREEN TOP
User.13: BOTTOM COPPER
User.15: INNER1 COPPER
User.16: INNER2 COPPER
User.18: GROUND 2
User.19: GROUND 3
User.20: GROUND 4
User.21: R223 | R265 | R267 | R268 | U42 | R296 | TP12 | TP34 | C176 | R318 | R316 | C175 | C177 | C111 | R260 | C159 | C164 | R259 | C110 | TP28 | R132 | C158 | C157 | C163 | TP32 | TP17 | R134 | R34 | R323 | TP13 | TP48 | TP14 | R158 | R181 | TP47 | TP78 | C144 | R151 | R229 | TP77 | L40 | C168 | TP76 | R207 | R206 | R117 | C131 | C142 | C257 | C130 | C254 | C132 | C262 | C167 | C186 | C187 | R205 | C136 | C258 | C255 | C128 | TP63 | TP60 | R305 | TP62 | TP61 | TP88 | U46 | R290 | R287 | R285 | TP89 | TP57 | TP58 | TP59 | R281 | TP87 | C224 | L49 | L50 | R112 | TP85 | C220 | C239 | C251 | C250 | C240 | C243 | J13 | TP86 | L48 | C223 | C232 | C241 | R280 | L47 | C222 | TP84 | TP80 | TP75 | R37 | R36 | R38 | R39 | TP51 | TP79 | TP20 | C183 | C182 | C184 | TP53 | TP18 | TP74 | TP44 | TP50 | TP52 | TP21 | R41 | R104 | R230 | TP19 | R102 | C51 | U7 | U38 | TP4 | TP25 | C194 | TP23 | TP24 | TP22 | C191 | R194 | TP2 | C213 | TP5 | TP6 | R31 | R46 | C71 | C67 | C85 | C81 | C83 | C69 | C79 | C180 | C65 | C90 | C88 | C89 | C87 | C75 | C73 | R30 | L12 | L22 | L21 | L11 | C76 | R25 | R26 | R203 | R308 | R204 | U3 | R74 | R72 | R66 | R64 | C92 | R77 | R78 | R70 | R76 | R68 | R69 | R75 | R67 | LR6 | LR8 | LR5 | LR7 | U28 | J29 | U6 | L14 | L26 | L24 | L16 | L30 | L29 | L20 | L19 | R73 | R63 | R71 | R65 | R295 | C155 | C217 | R315 | L41 | R266 | R314 | R313 | C166 | R297 | R310 | R298 | C267 | R317 | L43 | R139 | C151 | C152 | L42 | C153 | C150 | R89 | C162 | R183 | R166 | Q8 | Q7 | R91 | C160 | C109 | R172 | R182 | R130 | C145 | R8 | R324 | L38 | R136 | R90 | TP69 | R131 | C140 | C161 | R118 | C165 | R309 | L37 | TP33 | R227 | TP40 | R156 | C129 | C135 | R201 | R149 | C141 | R199 | C256 | C143 | R155 | C259 | C127 | TP56 | R148 | C137 | C260 | TP55 | R147 | R157 | C261 | C146 | R154 | R150 | TP54 | R146 | R153 | C264 | R145 | R152 | L51 | R282 | C247 | C235 | C230 | C238 | C242 | C236 | C229 | C237 | C246 | C231 | C221 | C248 | R322 | R321 | R61 | R40 | R43 | R105 | R58 | R51 | R53 | R44 | C63 | R59 | C193 | R42 | C192 | R101 | R197 | R45 | R196 | R228 | C62 | R193 | R195 | C61 | C86 | C82 | C72 | C68 | C74 | R231 | C84 | C80 | C70 | C66 | R28 | C91 | C78 | C77 | R24 | R224 | R226 | L27 | L18 | L17 | L28 | LR4 | LR3 | LR2 | LR1 | J27 | R240 | U49 | L25 | L23 | L15 | L13
User.22: REQUIREMENTS | 1. MANUFACTURE BOARD IAW (IN ACCORDANCE WITH) IPC-6012, CLASS 2. | 2. TOTAL BOARD THICKNESS: 62 MILS +/- 10% ALL MATERIAL SHALL BE | RoHS-COMPLIANT FR-4 OR EQUIVALENT | 3. COPPER PLATING ON WALL OF PLATED THROUGH HOLES SHALL BE 0.8 MIL MIN FOR CLASS 2. | 4. MINIMUM TRACE WIDTH: 5 MILS     MINIMUM SPACING: 5 MILS | 5. SOLDERMASK: | 5.1 LIQUID PHOTOIMAGEABLE (LPI) SOLDERMASK OVER BARE COPPER (SMOBC), | TOP AND BOTTOM SIDES | 5.2 COLOR: GREEN | 5.3 RESIZING FOR OPTIMAL MASK CLEARANCE TO CONDUCTIVE FEATURES PERMISSIBLE. | 6. HOLES: | 6.1 UNLESS OTHERWISE SPECIFIED ALL HOLE SIZES SHALL BE AS SPECIFIED | +/- 3 MILS. | 6.2 ALL HOLE SIZES FOR VIAS ARE MAXIMUM DIMENSIONS ONLY. | 7. SURFACE FINISH SHALL BE ELECTROLESS NICKEL IMMERSION GOLD (ENIG) | 8. DRC'S MUST BE RUN ON GERBERS BEFORE BUILDING BOARDS UNLESS PRIOR | APPROVAL IS GIVEN IN WRITING. | 9. BOARD SHALL BE ELECTRICALLY TESTED USING IPC-NETLIST FILE GIVEN | UNLESS PRIOR APPROVAL IS GIVEN IN WRITING. | 10. TOOLING RAILS WITH ROUTE-AND-RETAIN ARE REQUIRED ON PANEL FOR ASSEMBLY, | PANELIZATION IS DETERMINED BY VENDOR. ROUGH BOARD EDGES RESULTING FROM | DE-PANELIZATION SHALL BE SANDED SMOOTH. | 11. SILKSCREEN COLOR: WHITE | 12. CONTROLLED IMPEDANCE REQUIREMENTS: | 12.1 SINGLE ENDED: | LAYERS: TOP, INNER1, INNER2, BOTTOM | 50 OHMS +/- 5 OHMS ON ALL 5 MIL WIDE TRACES | 12.2 EDGE-COUPLED DIFFERENTIAL (100 OHMS): | LAYERS: TOP, BOTTOM | 100 OHMS +/- 10 OHMS ON 5.01 MIL WIDE TRACES WITH 9 MIL AIRGAP | 12.3 EDGE-COUPLED DIFFERENTIAL (90 OHMS): | 90 OHMS +/- 9 OHMS ON 5.3 MIL WIDE TRACES WITH 6 MIL AIRGAP | 13. REMOVAL OF NON-FUNCTIONAL PADS IS PERMISSIBLE. | 14. WARP OR TWIST OF BOARD SHALL NOT EXCEED 0.75% | 15. REMOVE ALL BURRS AND BREAK SHARP EDGES 10 MILS MAXIMUM.
User.23: NOTES: | 1. WORKMANSHIP TO BE ROHS COMPLIANT AND IN ACCORDANCE WITH (IAW) THE REQUIREMENTS OF IPC-A-610 (LATEST ISSUE), CLASS 2. | 2. MARKING | 2.1 MARK APPROPRIATE REVISION LEVEL IN AREA PROVIDED. USE MATERIALS AND METHODS AS OUTLINED IN MIL-STD-130(LATEST ISSUE), | SECTION 4.0, GENERAL REQUIREMENTS. | 2.2 USING BOM ITEM 2 AFFIX LABEL REPRESENTING THE SERIAL NUMBER IN AREA PROVIDED. | 3. SILKSCREEN DOTS ON DIODES INDICATE CATHODE PIN. | 4. ROUGH BOARD EDGES RESULTING FROM DE-PANELIZATION SHALL BE SANDED SMOOTH. | COMPONENTS VIEWED FROM TOP SIDE | COMPONENTS VIEWED FROM BOTTOM SIDE
User.24: LAYER 3 - INNER 1 - 1/2 OZ | LAYER 4 - GROUND 2 - 1 OZ | LAYER 5 - POWER 1 - 1 OZ | LAYER 6 - POWER 2 - 1 OZ | LAYER 7 - GROUND 3 - 1 OZ | LAYER 8 - INNER 2 - 1/2 OZ | LAYER 10 - BOTTOM - 1/2 OZ PLUS PLATING | LAYER 1 - TOP - 1/2 OZ PLUS PLATING | LAYER 2 - GROUND 1 - 1 OZ | LAYER 9 - GROUND 4 - 1 OZ | LAYER 10 SILKSCREEN | DIELECTRIC | LAYER 10 SOLDER MASK | LAYER 1 SILKSCREEN | LAYER 1 SOLDER MASK | 62.0 | + | - | 10% | LAYER STACKING CONFIGURATION | SCALE = NONE | DETAIL A
User.25: - | 07/19/17 | CHANGES PER BUG 2402 & 2435 | WAS
User.31: - | 07/19/17 | CHANGES PER BUGS 2402 & 2435 | WAS
User.37: POWER 2
User.38: C21 | C229 | R95 | TP11 | R161 | TP6 | C209 | TP12 | R173 | R172 | TP50 | TP32 | C202 | TP5 | TP25 | TP34 | TP17 | TP16 | TP20 | C129 | C130 | C131 | C132 | C124 | C128 | C29 | C26 | C23 | C34 | C33 | C166 | C17 | C15 | C16 | U11 | C144 | C162 | C39 | C181 | C107 | R32 | C141 | C142 | C24 | R35 | C42 | R26 | R24 | C164 | C80 | C79 | C20 | C51 | C176 | C90 | C48 | C89 | C60 | R6 | C50 | R4 | C18 | TP9 | C171 | C73 | C74 | R1 | C151 | C54 | C57 | R98 | C97 | R97 | C174 | C96 | C35 | C58 | R106 | R107 | R111 | R110 | R113 | R114 | R93 | R122 | TP51 | TP52 | TP53 | TP54 | TP55 | TP56 | TP10 | TP8 | C38 | C37 | C36 | R153 | R154 | C182 | C185 | C222 | R65 | R80 | R78 | R63 | R66 | R57 | R76 | R73 | R56 | R75 | R70 | R52 | R68 | R82 | R83 | R135 | C99 | C47 | C19 | C75 | C31 | TP60 | TP59 | R49 | C6 | R50 | R164 | R167 | R166 | C201 | TP13 | R168 | C224 | C62 | C63 | C226 | R174 | C66 | TP31 | TP61 | R175 | TP33 | TP43 | TP38 | TP15 | C64 | R128 | C8 | U16 | R36 | TP14 | R127 | R169 | R159 | R34 | J5 | R171 | C12 | R158 | R125 | R30 | R170 | C10 | R126 | R33 | C9 | C146 | C133 | C178 | C143 | C214 | C215 | C145 | C163 | C194 | E8 | C25 | R119 | L1 | C196 | C101 | E7 | C138 | C98 | C161 | C108 | E4 | C88 | C105 | TP2 | C100 | C104 | C106 | C140 | C165 | C103 | R23 | C87 | R19 | R22 | C44 | C78 | R20 | C86 | C177 | C159 | R21 | E5 | R18 | C180 | C158 | C77 | C81 | C82 | C175 | C91 | R12 | C43 | R14 | C135 | R13 | C76 | C56 | C217 | R11 | R136 | C173 | C154 | R17 | C155 | C156 | R41 | R2 | TP1 | C67 | C52 | C95 | R40 | C157 | C149 | C150 | TP4 | C170 | TP3 | C68 | C84 | C85 | C69 | TP44 | R121 | R102 | TP7 | C134 | C169 | E1 | E3 | C179 | C172 | C147 | C148 | C152 | TP45 | R163 | C183 | TP58 | TP47 | TP49 | R88 | TP37 | TP57 | SW1 | R48 | TP48 | R47 | R176 | TP46 | TP36 | R162 | TP29 | J1 | R134 | U19 | TP30 | C32 | C83 | C30 | C49 | C53
User.42: NOTES: | - DRILL SIZES LISTED IN LEGEND | ARE CONSIDERED FINISHED. | - VENDOR IS REQUIRED TO SELECT | TOOLING FOR OVERDRILLING. | FIGURE | FINISHED_SIZE | 8.0 | 12.0 | 12.99 | 14.96 | 25.59 | 35.43 | 40.0 | 41.34 | 62.99 | 72.83 | 133.86 | 146.85 | 55.12 | 125.98 | 33.46x25.59 | 43.31x23.62 | 51.18x23.62 | 59.06x32.68 | 118.11x31.5 | DRILL CHART: TOP to BOTTOM | ALL UNITS ARE IN MILS | ROTATION | - | 90.000 | 0.000 | PLATED | NON-PLATED | QTY | 903 | 201 | 16 | 36 | 7 | 1 | 12 | 19 | 4 | 18 | 6 | 2 | 1254 | TOTAL HOLES:
User.45: R223 | R265 | R267 | R268 | U42 | R296 | TP12 | TP34 | C176 | R318 | R316 | C175 | C177 | C111 | R260 | C159 | C164 | R259 | C110 | TP28 | R132 | C158 | C157 | C163 | TP32 | R134 | R34 | R323 | TP14 | R158 | R181 | TP47 | TP78 | C144 | R151 | R229 | TP77 | L40 | C168 | TP76 | R207 | R206 | R117 | C131 | C142 | C257 | C130 | C254 | C132 | C262 | C167 | C186 | C187 | R205 | C136 | C258 | C255 | C128 | TP63 | TP60 | R305 | TP62 | TP61 | U46 | TP88 | R290 | R287 | R285 | TP57 | TP58 | TP59 | TP89 | R281 | TP87 | C224 | L49 | L50 | R112 | TP85 | C220 | C239 | C251 | C250 | C240 | C243 | J13 | TP86 | L48 | C223 | C232 | C241 | R280 | L47 | C222 | TP84 | TP80 | TP75 | R37 | R36 | R38 | R39 | TP51 | TP79 | TP20 | C183 | C182 | C184 | TP53 | TP18 | TP74 | TP44 | TP50 | TP52 | TP21 | R230 | R41 | TP19 | R59 | C51 | U7 | U38 | TP4 | TP25 | C194 | TP23 | TP24 | TP22 | C191 | R194 | TP5 | TP6 | C213 | R31 | R46 | C71 | C67 | C85 | C81 | C83 | C69 | C79 | C180 | C65 | C90 | C88 | C89 | C87 | C75 | C73 | R30 | L12 | L22 | L21 | L11 | C76 | R25 | R26 | R203 | R308 | R204 | U3 | R74 | R72 | R66 | R64 | C92 | R77 | R78 | R70 | R76 | R68 | R69 | R75 | R67 | LR6 | LR8 | LR5 | LR7 | U28 | U6 | U49 | L14 | L26 | L24 | L16 | L30 | L29 | L20 | L19 | R73 | R63 | R71 | R65 | R295 | C155 | C217 | R315 | L41 | R266 | R314 | R313 | C166 | R297 | R310 | R298 | C267 | R317 | L43 | R139 | C151 | C152 | L42 | C153 | C150 | R89 | C162 | R183 | R166 | Q8 | Q7 | R91 | C160 | C109 | R172 | R182 | R130 | C145 | R8 | R324 | R136 | R90 | TP69 | R131 | L38 | TP17 | C140 | C161 | R118 | TP13 | TP48 | C165 | R309 | TP33 | L37 | R227 | TP40 | R156 | C129 | C135 | R201 | R149 | C141 | R199 | C256 | C143 | R155 | C259 | C127 | TP56 | R148 | C137 | C260 | TP55 | R147 | R157 | C261 | C146 | R154 | R150 | TP54 | R146 | R153 | C264 | R145 | R152 | L51 | R282 | C247 | C235 | C230 | C238 | C242 | C236 | C229 | C237 | C246 | C231 | C221 | C248 | R322 | R321 | R61 | R40 | R43 | R58 | R51 | R105 | R53 | R104 | R44 | C63 | R102 | C193 | R101 | R42 | C192 | R197 | R45 | R196 | R240 | R228 | C62 | R193 | R195 | C61 | C86 | C82 | C72 | C68 | C74 | R231 | C84 | C80 | C70 | C66 | R28 | C91 | C78 | C77 | R24 | R224 | R226 | L27 | L18 | L17 | L28 | LR4 | LR3 | LR2 | LR1 | J27 | L25 | L23 | L15 | L13
